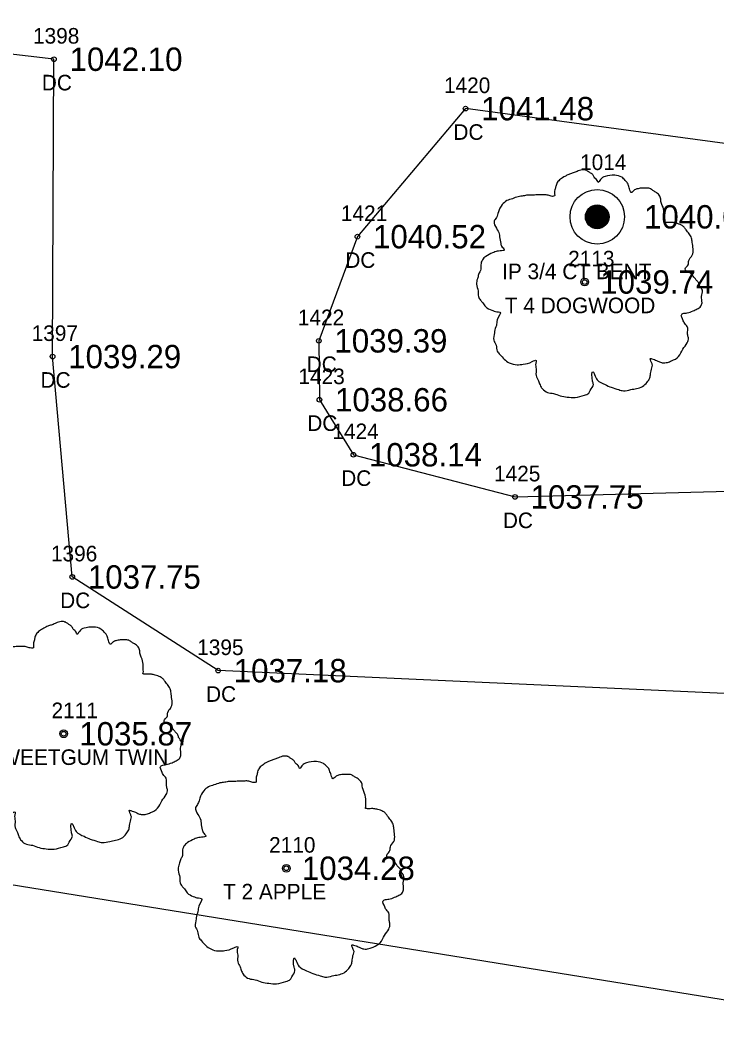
# Model space of a CAD drawing. Extents: x 1578957 to 1581675, y 1115963 to 1120391.
# Drawn here: x 1579731.3 to 1579776, y 1117737.6 to 1117802 of the extents above; entities that cross this region are included whole.
import ezdxf

# ---------------------------------------------------------------- set-up
doc = ezdxf.new("R2010")
doc.units = 0
for name, color, linetype in [('RD_EX_Conc', 7, 'Continuous'), ('RD_EX_Conc_txCode', 7, 'Continuous'), ('RD_EX_DV_Prop_txCode', 7, 'Continuous'), ('RD_EX_DV_PropPin', 7, 'Continuous'), ('RD_EX_TX_Conc_ELEV', 7, 'Continuous'), ('RD_EX_TX_DV_Prop_ELEV', 7, 'Continuous'), ('RD_EX_TX_VEG_ELEV', 7, 'Continuous'), ('RD_EX_VEG', 7, 'Continuous'), ('RD_EX_VEG_txCode', 7, 'Continuous'), ('RD_SMD_Locator', 7, 'Continuous')]:
    doc.layers.add(name, color=color, linetype=linetype)

msp = doc.modelspace()

# ---------------------------------------------------------------- linework, layer by layer
at = {"layer": 'RD_EX_Conc'}
for points in [[(1579796.546, 1117760.818), (1579779.297, 1117758.713), (1579743.97, 1117760.315), (1579734.607, 1117766.323), (1579733.345, 1117780.457), (1579733.432, 1117799.525), (1579711.989, 1117802.034), (1579710.024, 1117801.624), (1579709.026, 1117799.89), (1579702.7, 1117801.096)], [(1579779.975, 1117793.644), (1579759.848, 1117796.355), (1579752.909, 1117788.146), (1579750.432, 1117781.466), (1579750.469, 1117777.688), (1579752.647, 1117774.161), (1579763.024, 1117771.454), (1579777.545, 1117771.842), (1579791.001, 1117773.674)]]:
    msp.add_lwpolyline(points, dxfattribs=at)
at = {"layer": 'RD_EX_DV_PropPin'}
for p, q in [((1579767.602, 1117789.121), (1579767.602, 1117789.717)), ((1579767.638, 1117789.05), (1579767.638, 1117789.789)), ((1579767.673, 1117788.993), (1579767.673, 1117789.846)), ((1579767.708, 1117788.945), (1579767.708, 1117789.894)), ((1579767.743, 1117788.904), (1579767.743, 1117789.934)), ((1579767.778, 1117788.869), (1579767.778, 1117789.97)), ((1579767.813, 1117788.837), (1579767.813, 1117790.002)), ((1579767.848, 1117788.81), (1579767.848, 1117790.029)), ((1579767.883, 1117788.785), (1579767.883, 1117790.054)), ((1579767.918, 1117788.763), (1579767.918, 1117790.076)), ((1579767.953, 1117788.744), (1579767.953, 1117790.095)), ((1579767.988, 1117788.727), (1579767.988, 1117790.112)), ((1579768.023, 1117788.712), (1579768.023, 1117790.127)), ((1579768.058, 1117788.699), (1579768.058, 1117790.14)), ((1579768.093, 1117788.688), (1579768.093, 1117790.151)), ((1579768.128, 1117788.679), (1579768.128, 1117790.16)), ((1579768.163, 1117788.671), (1579768.163, 1117790.167)), ((1579768.198, 1117788.666), (1579768.198, 1117790.173)), ((1579768.233, 1117788.662), (1579768.233, 1117790.177)), ((1579768.268, 1117788.659), (1579768.268, 1117790.18)), ((1579768.303, 1117788.658), (1579768.303, 1117790.18)), ((1579768.338, 1117788.659), (1579768.338, 1117790.18)), ((1579768.373, 1117788.662), (1579768.373, 1117790.177)), ((1579768.408, 1117788.666), (1579768.408, 1117790.173)), ((1579768.443, 1117788.671), (1579768.443, 1117790.167)), ((1579768.478, 1117788.679), (1579768.478, 1117790.16)), ((1579768.513, 1117788.688), (1579768.513, 1117790.151)), ((1579768.548, 1117788.699), (1579768.548, 1117790.14)), ((1579768.583, 1117788.712), (1579768.583, 1117790.127)), ((1579768.618, 1117788.727), (1579768.618, 1117790.112)), ((1579768.653, 1117788.744), (1579768.653, 1117790.095)), ((1579768.688, 1117788.763), (1579768.688, 1117790.076)), ((1579768.723, 1117788.785), (1579768.723, 1117790.054)), ((1579768.758, 1117788.81), (1579768.758, 1117790.029)), ((1579768.793, 1117788.837), (1579768.793, 1117790.002)), ((1579768.828, 1117788.869), (1579768.828, 1117789.97)), ((1579768.863, 1117788.904), (1579768.863, 1117789.934)), ((1579768.898, 1117788.945), (1579768.898, 1117789.894)), ((1579768.933, 1117788.993), (1579768.933, 1117789.846)), ((1579768.968, 1117789.05), (1579768.968, 1117789.789)), ((1579769.003, 1117789.121), (1579769.003, 1117789.717)), ((1579767.567, 1117789.223), (1579767.567, 1117789.616)), ((1579769.038, 1117789.223), (1579769.038, 1117789.616))]:
    msp.add_line(p, q, dxfattribs=at)
for radius in [1.75, 0.761]:
    msp.add_circle((1579768.303, 1117789.419), radius, dxfattribs=at)
at = {"layer": 'RD_EX_VEG'}
msp.add_lwpolyline([(1579862.335, 1117508.136), (1579987.98, 1117577.137), (1580030.014, 1117601.023), (1580092.8, 1117606.943), (1580099.438, 1117660.216), (1579997.235, 1117695.776), (1579947.95, 1117691.884), (1579838.071, 1117719.77), (1579796.802, 1117753.004), (1579780.494, 1117738.535), (1579705.634, 1117750.62)], dxfattribs=at)
for centre, radius in [((1579767.496, 1117785.238), 0.25), ((1579767.484, 1117785.219), 0.0001), ((1579734.054, 1117756.268), 0.25), ((1579734.042, 1117756.249), 0.0001), ((1579748.342, 1117747.643), 0.25), ((1579748.329, 1117747.624), 0.0001)]:
    msp.add_circle(centre, radius, dxfattribs=at)
for points in [[(1579767.628, 1117792.405), (1579767.328, 1117792.43), (1579767.003, 1117792.33), (1579766.754, 1117792.23), (1579766.529, 1117792.155), (1579766.304, 1117792.055), (1579766.004, 1117791.88), (1579765.779, 1117791.68), (1579765.654, 1117791.43), (1579765.604, 1117791.205), (1579765.554, 1117790.931), (1579765.554, 1117790.756), (1579765.429, 1117790.731), (1579765.279, 1117790.756), (1579765.029, 1117790.831), (1579764.779, 1117790.831), (1579764.529, 1117790.831), (1579764.18, 1117790.806), (1579763.83, 1117790.806), (1579763.555, 1117790.756), (1579763.23, 1117790.706), (1579762.855, 1117790.581), (1579762.505, 1117790.456), (1579762.206, 1117790.206), (1579761.956, 1117789.731), (1579761.831, 1117789.381), (1579761.681, 1117789.131), (1579761.831, 1117788.682), (1579762.006, 1117788.332), (1579762.031, 1117788.132), (1579762.106, 1117787.707), (1579762.206, 1117787.482), (1579762.33, 1117787.282), (1579762.256, 1117787.257), (1579761.881, 1117787.207), (1579761.581, 1117787.107), (1579761.156, 1117786.882), (1579760.931, 1117786.657), (1579760.831, 1117786.332), (1579760.806, 1117785.983), (1579760.706, 1117785.783), (1579760.631, 1117785.508), (1579760.606, 1117785.433), (1579760.556, 1117785.108), (1579760.656, 1117784.658), (1579760.681, 1117784.308), (1579760.806, 1117784.083), (1579760.956, 1117783.909), (1579761.131, 1117783.659), (1579761.531, 1117783.434), (1579761.856, 1117783.334), (1579762.056, 1117783.309), (1579761.881, 1117782.809), (1579761.831, 1117782.459), (1579761.706, 1117782.059), (1579761.706, 1117781.984), (1579761.656, 1117781.51), (1579761.806, 1117781.185), (1579761.881, 1117780.81), (1579762.056, 1117780.585), (1579762.33, 1117780.285), (1579762.655, 1117780.06), (1579763.155, 1117779.935), (1579763.555, 1117779.96), (1579764.13, 1117780.135), (1579764.38, 1117780.21), (1579764.355, 1117780.035), (1579764.38, 1117779.66), (1579764.38, 1117779.236), (1579764.529, 1117778.911), (1579764.629, 1117778.636), (1579764.779, 1117778.386), (1579765.104, 1117778.161), (1579765.504, 1117778.086), (1579765.929, 1117777.936), (1579766.379, 1117777.861), (1579766.878, 1117777.836), (1579767.478, 1117777.986), (1579767.753, 1117778.111), (1579767.853, 1117778.286), (1579768.053, 1117778.661), (1579768.003, 1117778.886), (1579768.028, 1117779.486), (1579768.128, 1117779.311), (1579768.303, 1117778.961), (1579768.803, 1117778.661), (1579769.202, 1117778.486), (1579769.677, 1117778.336), (1579769.977, 1117778.261), (1579770.452, 1117778.336), (1579770.827, 1117778.411), (1579771.202, 1117778.536), (1579771.501, 1117778.811), (1579771.676, 1117779.086), (1579771.726, 1117779.361), (1579771.801, 1117779.735), (1579771.851, 1117779.91)], [(1579771.851, 1117779.91), (1579771.776, 1117780.085), (1579771.726, 1117780.335), (1579771.801, 1117780.31), (1579771.976, 1117780.26), (1579772.251, 1117780.135), (1579772.476, 1117780.06), (1579772.801, 1117780.085), (1579773.076, 1117780.185), (1579773.526, 1117780.46), (1579773.8, 1117780.935), (1579774.075, 1117781.335), (1579774.15, 1117781.66), (1579774.1, 1117781.884), (1579774.075, 1117782.384), (1579773.875, 1117782.634), (1579773.825, 1117782.759), (1579773.725, 1117783.159), (1579773.8, 1117783.209), (1579774.075, 1117783.259), (1579774.45, 1117783.384), (1579774.725, 1117783.509), (1579774.95, 1117783.684), (1579775.025, 1117783.909), (1579775, 1117784.308), (1579775.05, 1117784.708), (1579774.975, 1117784.858), (1579774.875, 1117785.008), (1579774.8, 1117785.208), (1579774.65, 1117785.358), (1579774.55, 1117785.508), (1579774.45, 1117785.608), (1579774.325, 1117785.758), (1579774.15, 1117785.883), (1579774, 1117785.933), (1579773.95, 1117786.083), (1579774.1, 1117786.283), (1579774.15, 1117786.382), (1579774.175, 1117786.607), (1579774.4, 1117786.957), (1579774.45, 1117787.357), (1579774.4, 1117787.782), (1579774.35, 1117788.057), (1579774.2, 1117788.332), (1579774, 1117788.582), (1579773.875, 1117788.756), (1579773.7, 1117788.881), (1579773.376, 1117789.006), (1579773.126, 1117789.056), (1579772.776, 1117789.056), (1579772.576, 1117789.106), (1579772.601, 1117789.156), (1579772.601, 1117789.306), (1579772.601, 1117789.581), (1579772.526, 1117790.031), (1579772.376, 1117790.531), (1579772.376, 1117790.556), (1579772.276, 1117790.806), (1579772.051, 1117791.005), (1579771.876, 1117791.105), (1579771.676, 1117791.23), (1579771.426, 1117791.255), (1579771.127, 1117791.255), (1579770.852, 1117791.205), (1579770.652, 1117791.105), (1579770.477, 1117790.98), (1579770.402, 1117791.13), (1579770.302, 1117791.43), (1579770.252, 1117791.58), (1579770.102, 1117791.755), (1579769.877, 1117791.955), (1579769.427, 1117792.08), (1579768.803, 1117792.005), (1579768.503, 1117791.805), (1579768.353, 1117791.63), (1579768.303, 1117791.755), (1579768.103, 1117791.955), (1579768.003, 1117792.13), (1579767.828, 1117792.255), (1579767.678, 1117792.355), (1579767.578, 1117792.405)], [(1579734.186, 1117763.435), (1579733.886, 1117763.46), (1579733.561, 1117763.36), (1579733.312, 1117763.26), (1579733.087, 1117763.185), (1579732.862, 1117763.085), (1579732.562, 1117762.91), (1579732.337, 1117762.71), (1579732.212, 1117762.46), (1579732.162, 1117762.235), (1579732.112, 1117761.96), (1579732.112, 1117761.785), (1579731.987, 1117761.76), (1579731.837, 1117761.785), (1579731.587, 1117761.86), (1579731.337, 1117761.86), (1579731.087, 1117761.86), (1579730.738, 1117761.835), (1579730.388, 1117761.835), (1579730.113, 1117761.785), (1579729.788, 1117761.736), (1579729.413, 1117761.611), (1579729.063, 1117761.486), (1579728.764, 1117761.236), (1579728.514, 1117760.761), (1579728.389, 1117760.411), (1579728.239, 1117760.161), (1579728.389, 1117759.711), (1579728.564, 1117759.362), (1579728.589, 1117759.162), (1579728.664, 1117758.737), (1579728.764, 1117758.512), (1579728.888, 1117758.312), (1579728.814, 1117758.287), (1579728.439, 1117758.237), (1579728.139, 1117758.137), (1579727.714, 1117757.912), (1579727.489, 1117757.687), (1579727.389, 1117757.362), (1579727.364, 1117757.013), (1579727.264, 1117756.813), (1579727.189, 1117756.538), (1579727.164, 1117756.463), (1579727.114, 1117756.138), (1579727.214, 1117755.688), (1579727.239, 1117755.338), (1579727.364, 1117755.113), (1579727.514, 1117754.939), (1579727.689, 1117754.689), (1579728.089, 1117754.464), (1579728.414, 1117754.364), (1579728.614, 1117754.339), (1579728.439, 1117753.839), (1579728.389, 1117753.489), (1579728.264, 1117753.089), (1579728.264, 1117753.014), (1579728.214, 1117752.54), (1579728.364, 1117752.215), (1579728.439, 1117751.84), (1579728.614, 1117751.615), (1579728.888, 1117751.315), (1579729.213, 1117751.09), (1579729.713, 1117750.965), (1579730.113, 1117750.99), (1579730.688, 1117751.165), (1579730.938, 1117751.24), (1579730.913, 1117751.065), (1579730.938, 1117750.69), (1579730.938, 1117750.266), (1579731.087, 1117749.941), (1579731.187, 1117749.666), (1579731.337, 1117749.416), (1579731.662, 1117749.191), (1579732.062, 1117749.116), (1579732.487, 1117748.966), (1579732.937, 1117748.891), (1579733.436, 1117748.866), (1579734.036, 1117749.016), (1579734.311, 1117749.141), (1579734.411, 1117749.316), (1579734.611, 1117749.691), (1579734.561, 1117749.916), (1579734.586, 1117750.515), (1579734.686, 1117750.34), (1579734.861, 1117749.991), (1579735.361, 1117749.691), (1579735.76, 1117749.516), (1579736.235, 1117749.366), (1579736.535, 1117749.291), (1579737.01, 1117749.366), (1579737.385, 1117749.441), (1579737.76, 1117749.566), (1579738.059, 1117749.841), (1579738.234, 1117750.116), (1579738.284, 1117750.39), (1579738.359, 1117750.765), (1579738.409, 1117750.94)], [(1579738.409, 1117750.94), (1579738.334, 1117751.115), (1579738.284, 1117751.365), (1579738.359, 1117751.34), (1579738.534, 1117751.29), (1579738.809, 1117751.165), (1579739.034, 1117751.09), (1579739.359, 1117751.115), (1579739.634, 1117751.215), (1579740.084, 1117751.49), (1579740.358, 1117751.965), (1579740.633, 1117752.365), (1579740.708, 1117752.689), (1579740.658, 1117752.914), (1579740.633, 1117753.414), (1579740.433, 1117753.664), (1579740.383, 1117753.789), (1579740.283, 1117754.189), (1579740.358, 1117754.239), (1579740.633, 1117754.289), (1579741.008, 1117754.414), (1579741.283, 1117754.539), (1579741.508, 1117754.714), (1579741.583, 1117754.939), (1579741.558, 1117755.338), (1579741.608, 1117755.738), (1579741.533, 1117755.888), (1579741.433, 1117756.038), (1579741.358, 1117756.238), (1579741.208, 1117756.388), (1579741.108, 1117756.538), (1579741.008, 1117756.638), (1579740.883, 1117756.788), (1579740.708, 1117756.913), (1579740.558, 1117756.963), (1579740.508, 1117757.113), (1579740.658, 1117757.312), (1579740.708, 1117757.412), (1579740.733, 1117757.637), (1579740.958, 1117757.987), (1579741.008, 1117758.387), (1579740.958, 1117758.812), (1579740.908, 1117759.087), (1579740.758, 1117759.362), (1579740.558, 1117759.611), (1579740.433, 1117759.786), (1579740.258, 1117759.911), (1579739.934, 1117760.036), (1579739.684, 1117760.086), (1579739.334, 1117760.086), (1579739.134, 1117760.136), (1579739.159, 1117760.186), (1579739.159, 1117760.336), (1579739.159, 1117760.611), (1579739.084, 1117761.061), (1579738.934, 1117761.561), (1579738.934, 1117761.586), (1579738.834, 1117761.835), (1579738.609, 1117762.035), (1579738.434, 1117762.135), (1579738.234, 1117762.26), (1579737.984, 1117762.285), (1579737.685, 1117762.285), (1579737.41, 1117762.235), (1579737.21, 1117762.135), (1579737.035, 1117762.01), (1579736.96, 1117762.16), (1579736.86, 1117762.46), (1579736.81, 1117762.61), (1579736.66, 1117762.785), (1579736.435, 1117762.985), (1579735.985, 1117763.11), (1579735.361, 1117763.035), (1579735.061, 1117762.835), (1579734.911, 1117762.66), (1579734.861, 1117762.785), (1579734.661, 1117762.985), (1579734.561, 1117763.16), (1579734.386, 1117763.285), (1579734.236, 1117763.385), (1579734.136, 1117763.435)], [(1579748.474, 1117754.81), (1579748.174, 1117754.835), (1579747.849, 1117754.735), (1579747.599, 1117754.635), (1579747.374, 1117754.56), (1579747.149, 1117754.46), (1579746.849, 1117754.285), (1579746.625, 1117754.085), (1579746.5, 1117753.836), (1579746.45, 1117753.611), (1579746.4, 1117753.336), (1579746.4, 1117753.161), (1579746.275, 1117753.136), (1579746.125, 1117753.161), (1579745.875, 1117753.236), (1579745.625, 1117753.236), (1579745.375, 1117753.236), (1579745.025, 1117753.211), (1579744.675, 1117753.211), (1579744.401, 1117753.161), (1579744.076, 1117753.111), (1579743.701, 1117752.986), (1579743.351, 1117752.861), (1579743.051, 1117752.611), (1579742.801, 1117752.136), (1579742.676, 1117751.786), (1579742.526, 1117751.537), (1579742.676, 1117751.087), (1579742.851, 1117750.737), (1579742.876, 1117750.537), (1579742.951, 1117750.112), (1579743.051, 1117749.887), (1579743.176, 1117749.687), (1579743.101, 1117749.662), (1579742.726, 1117749.612), (1579742.426, 1117749.512), (1579742.002, 1117749.288), (1579741.777, 1117749.063), (1579741.677, 1117748.738), (1579741.652, 1117748.388), (1579741.552, 1117748.188), (1579741.477, 1117747.913), (1579741.452, 1117747.838), (1579741.402, 1117747.513), (1579741.502, 1117747.063), (1579741.527, 1117746.714), (1579741.652, 1117746.489), (1579741.802, 1117746.314), (1579741.977, 1117746.064), (1579742.376, 1117745.839), (1579742.701, 1117745.739), (1579742.901, 1117745.714), (1579742.726, 1117745.214), (1579742.676, 1117744.864), (1579742.551, 1117744.465), (1579742.551, 1117744.39), (1579742.501, 1117743.915), (1579742.651, 1117743.59), (1579742.726, 1117743.215), (1579742.901, 1117742.99), (1579743.176, 1117742.69), (1579743.501, 1117742.466), (1579744.001, 1117742.341), (1579744.401, 1117742.366), (1579744.975, 1117742.54), (1579745.225, 1117742.615), (1579745.2, 1117742.441), (1579745.225, 1117742.066), (1579745.225, 1117741.641), (1579745.375, 1117741.316), (1579745.475, 1117741.041), (1579745.625, 1117740.791), (1579745.95, 1117740.566), (1579746.35, 1117740.491), (1579746.774, 1117740.341), (1579747.224, 1117740.266), (1579747.724, 1117740.241), (1579748.324, 1117740.391), (1579748.599, 1117740.516), (1579748.699, 1117740.691), (1579748.899, 1117741.066), (1579748.849, 1117741.291), (1579748.874, 1117741.891), (1579748.973, 1117741.716), (1579749.148, 1117741.366), (1579749.648, 1117741.066), (1579750.048, 1117740.891), (1579750.523, 1117740.741), (1579750.823, 1117740.666), (1579751.297, 1117740.741), (1579751.672, 1117740.816), (1579752.047, 1117740.941), (1579752.347, 1117741.216), (1579752.522, 1117741.491), (1579752.572, 1117741.766), (1579752.647, 1117742.141), (1579752.697, 1117742.316)], [(1579752.697, 1117742.316), (1579752.622, 1117742.491), (1579752.572, 1117742.74), (1579752.647, 1117742.715), (1579752.822, 1117742.665), (1579753.097, 1117742.54), (1579753.322, 1117742.466), (1579753.646, 1117742.491), (1579753.921, 1117742.59), (1579754.371, 1117742.865), (1579754.646, 1117743.34), (1579754.921, 1117743.74), (1579754.996, 1117744.065), (1579754.946, 1117744.29), (1579754.921, 1117744.789), (1579754.721, 1117745.039), (1579754.671, 1117745.164), (1579754.571, 1117745.564), (1579754.646, 1117745.614), (1579754.921, 1117745.664), (1579755.296, 1117745.789), (1579755.571, 1117745.914), (1579755.796, 1117746.089), (1579755.87, 1117746.314), (1579755.846, 1117746.714), (1579755.895, 1117747.113), (1579755.821, 1117747.263), (1579755.721, 1117747.413), (1579755.646, 1117747.613), (1579755.496, 1117747.763), (1579755.396, 1117747.913), (1579755.296, 1117748.013), (1579755.171, 1117748.163), (1579754.996, 1117748.288), (1579754.846, 1117748.338), (1579754.796, 1117748.488), (1579754.946, 1117748.688), (1579754.996, 1117748.788), (1579755.021, 1117749.013), (1579755.246, 1117749.362), (1579755.296, 1117749.762), (1579755.246, 1117750.187), (1579755.196, 1117750.462), (1579755.046, 1117750.737), (1579754.846, 1117750.987), (1579754.721, 1117751.162), (1579754.546, 1117751.287), (1579754.221, 1117751.412), (1579753.971, 1117751.462), (1579753.621, 1117751.462), (1579753.422, 1117751.512), (1579753.447, 1117751.562), (1579753.447, 1117751.711), (1579753.447, 1117751.986), (1579753.372, 1117752.436), (1579753.222, 1117752.936), (1579753.222, 1117752.961), (1579753.122, 1117753.211), (1579752.897, 1117753.411), (1579752.722, 1117753.511), (1579752.522, 1117753.636), (1579752.272, 1117753.661), (1579751.972, 1117753.661), (1579751.697, 1117753.611), (1579751.497, 1117753.511), (1579751.322, 1117753.386), (1579751.247, 1117753.536), (1579751.148, 1117753.836), (1579751.098, 1117753.985), (1579750.948, 1117754.16), (1579750.723, 1117754.36), (1579750.273, 1117754.485), (1579749.648, 1117754.41), (1579749.348, 1117754.21), (1579749.198, 1117754.035), (1579749.148, 1117754.16), (1579748.948, 1117754.36), (1579748.849, 1117754.535), (1579748.674, 1117754.66), (1579748.524, 1117754.76), (1579748.424, 1117754.81)]]:
    msp.add_spline(points, degree=3, dxfattribs=at)
at = {"layer": 'RD_SMD_Locator'}
for centre in [(1579733.432, 1117799.525), (1579759.848, 1117796.355), (1579768.303, 1117789.419), (1579752.909, 1117788.146), (1579767.496, 1117785.238), (1579750.432, 1117781.466), (1579733.345, 1117780.457), (1579750.469, 1117777.688), (1579752.647, 1117774.161), (1579763.024, 1117771.454), (1579734.607, 1117766.323), (1579743.97, 1117760.315), (1579734.054, 1117756.268), (1579748.342, 1117747.643)]:
    msp.add_circle(centre, 0.15, dxfattribs=at)

# ---------------------------------------------------------------- texts
at = {"layer": 'RD_EX_Conc_txCode'}
for s, p in [('1398', (1579732.085, 1117800.525)), ('DC', (1579732.652, 1117797.525)), ('1420', (1579758.462, 1117797.355)), ('DC', (1579759.068, 1117794.355)), ('1421', (1579751.846, 1117789.146)), ('DC', (1579752.13, 1117786.146)), ('1422', (1579749.085, 1117782.466)), ('1397', (1579731.998, 1117781.457)), ('DC', (1579749.652, 1117779.466)), ('DC', (1579732.565, 1117778.457)), ('1423', (1579749.122, 1117778.688)), ('DC', (1579749.689, 1117775.688)), ('1424', (1579751.301, 1117775.161)), ('DC', (1579751.867, 1117772.161)), ('1425', (1579761.677, 1117772.454)), ('DC', (1579762.244, 1117769.454)), ('1396', (1579733.237, 1117767.323)), ('DC', (1579733.828, 1117764.323)), ('1395', (1579742.624, 1117761.315)), ('DC', (1579743.191, 1117758.315))]:
    msp.add_text(s, height=1, dxfattribs=at).set_placement(p)
at = {"layer": 'RD_EX_DV_Prop_txCode'}
for s, p in [('1014', (1579767.2, 1117792.419)), ('IP 3/4 CT BENT', (1579762.193, 1117785.419))]:
    msp.add_text(s, height=1, dxfattribs=at).set_placement(p)
at = {"layer": 'RD_EX_TX_Conc_ELEV'}
for s, p in [('1042.10', (1579734.432, 1117798.775)), ('1041.48', (1579760.848, 1117795.605)), ('1040.52', (1579753.909, 1117787.396)), ('1039.39', (1579751.432, 1117780.716)), ('1039.29', (1579734.345, 1117779.707)), ('1038.66', (1579751.469, 1117776.938)), ('1038.14', (1579753.647, 1117773.411)), ('1037.75', (1579764.024, 1117770.704)), ('1037.75', (1579735.607, 1117765.573)), ('1037.18', (1579744.97, 1117759.565))]:
    msp.add_text(s, height=1.5, dxfattribs=at).set_placement(p)
at = {"layer": 'RD_EX_TX_DV_Prop_ELEV'}
msp.add_text('1040.01', height=1.5, dxfattribs=at).set_placement((1579771.303, 1117788.669))
at = {"layer": 'RD_EX_TX_VEG_ELEV'}
for s, p in [('1039.74', (1579768.496, 1117784.488)), ('1035.87', (1579735.054, 1117755.518)), ('1034.28', (1579749.342, 1117746.893))]:
    msp.add_text(s, height=1.5, dxfattribs=at).set_placement(p)
at = {"layer": 'RD_EX_VEG_txCode'}
for s, p in [('2113', (1579766.433, 1117786.238)), ('T 4 DOGWOOD', (1579762.37, 1117783.238)), ('2111', (1579733.275, 1117757.268)), ('T 16 SWEETGUM TWIN', (1579726.054, 1117754.268)), ('2110', (1579747.239, 1117748.643)), ('T 2 APPLE', (1579744.283, 1117745.643))]:
    msp.add_text(s, height=1, dxfattribs=at).set_placement(p)

doc.saveas('drawing.dxf')
